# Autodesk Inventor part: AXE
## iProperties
Shininess: 64.0
Length Units: 11269
Angle Units: 11279
Time Units: 11290
Mass Units: 11283
Length Display Precision: 3
Angle Display Precision: 2
Compacted: True
Part Number: AXE
Document SubType Name: Modeling
Created: 2005-04
Material: Par défaut
Designer: Flavien MARTY
Density: 0.0
Volumn: 0.0
Area: 0.0
PropertySet Name: Model Information
Control State: 0
Master: False
Checked Out: False
Author: Flavien MARTY
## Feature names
1. Base1
